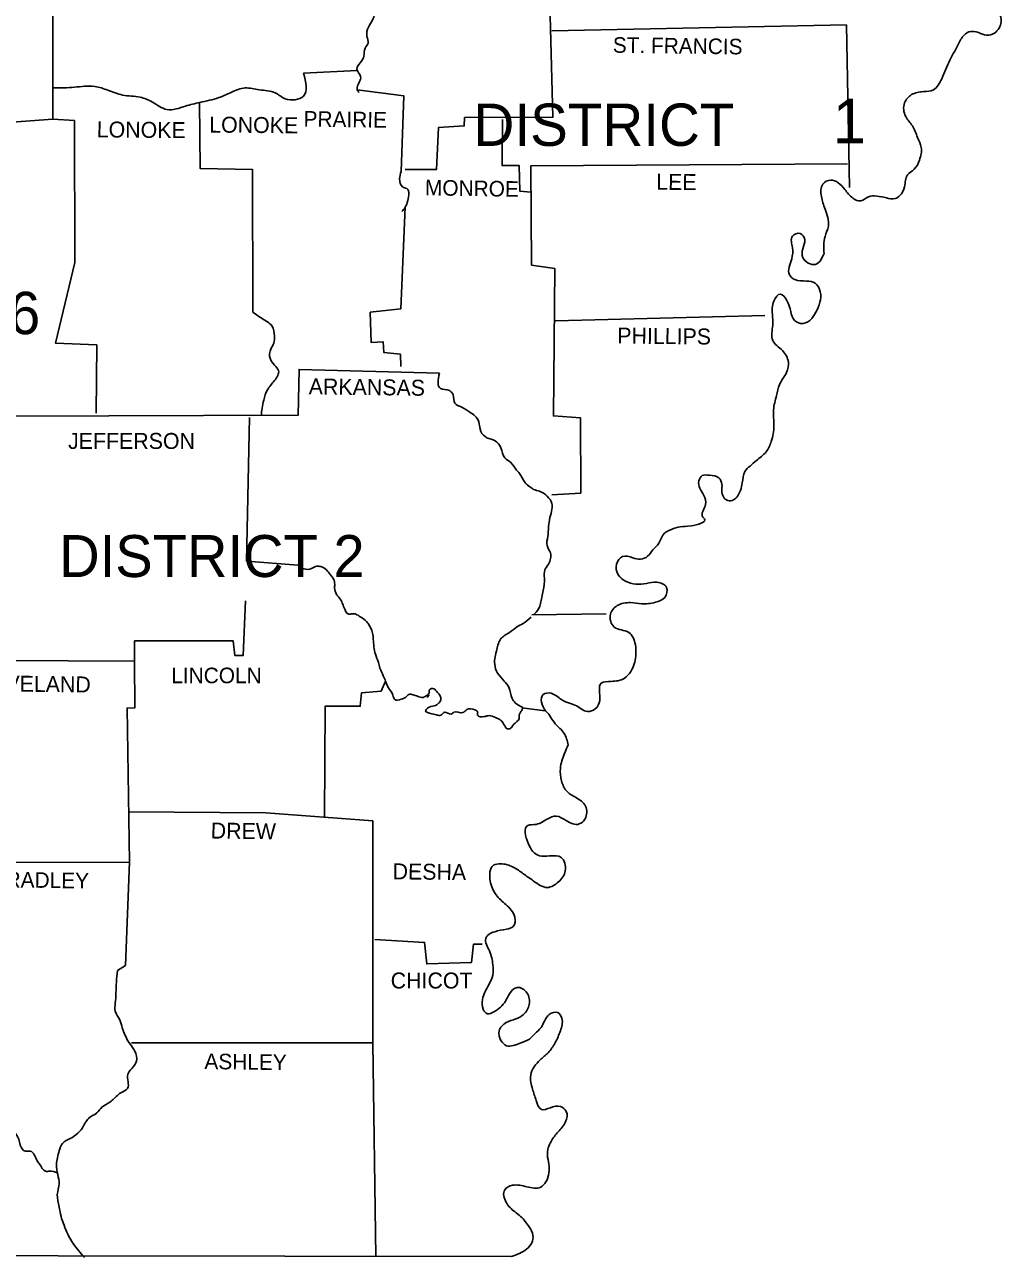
# Model space of a CAD drawing. Extents: x -549 to 3324, y -742 to 2142.
# Drawn here: x 2751.9 to 3009.3, y 1337.5 to 1662.3 of the extents above; entities that cross this region are included whole.
import ezdxf

# ---------------------------------------------------------------- set-up
doc = ezdxf.new("R2010")
doc.units = 0
for name, color, linetype in [('1', 7, 'Continuous'), ('2', 7, 'Continuous'), ('3', 7, 'Continuous')]:
    doc.layers.add(name, color=color, linetype=linetype)

msp = doc.modelspace()

# ---------------------------------------------------------------- linework, layer by layer
at = {"layer": '1'}
msp.add_line((2885.59, 1506.74), (2905.16, 1507.03), dxfattribs=at)
for points in [[(2752.92, 1860.82), (2753.12, 1837.54), (2751.45, 1837.44), (2751.75, 1813.08), (2744.9, 1812.1), (2745.49, 1805.54), (2747.83, 1802.51), (2747.64, 1794.78), (2734.33, 1794.29), (2733.84, 1782.36), (2721.71, 1781.96), (2721.12, 1767.48), (2721.81, 1766.31), (2722.1, 1743.22), (2743.04, 1741.85), (2742.75, 1690.29), (2759.38, 1689.8), (2759.38, 1637.36), (2746.27, 1636.38), (2745.29, 1624.83), (2723.28, 1624.73)], [(2889.7, 1691.46), (2891.17, 1637.84), (2867.89, 1637.75), (2867.79, 1635.59), (2861.04, 1635.2), (2860.45, 1624.05), (2852.23, 1624.05)], [(2890.88, 1660.64), (2968.56, 1662.21)], [(2968.56, 1662.21), (2969.35, 1619.35)], [(2825.42, 1649.49), (2839.61, 1650.17)], [(2839.61, 1645.08), (2851.84, 1643.52), (2851.15, 1623.56)], [(2798.03, 1641.86), (2798.22, 1624.34), (2812.02, 1624.05), (2812.12, 1586.48)], [(2759.38, 1637.36), (2765.05, 1636.96), (2765.15, 1599.59), (2760.06, 1578.36), (2770.93, 1577.87), (2770.83, 1559.87)], [(2877.87, 1637.26), (2877.77, 1625.13), (2882.27, 1625.13), (2882.46, 1618.37), (2885.3, 1618.08)], [(2890.88, 1538.34), (2898.51, 1538.83), (2898.41, 1558.69), (2891.27, 1559.18), (2891.66, 1598.02), (2885.5, 1598.9), (2885.3, 1625.03), (2968.76, 1625.61)], [(2852.23, 1614.17), (2851.06, 1587.36), (2843.03, 1586.48), (2843.23, 1578.55), (2846.46, 1578.65), (2846.56, 1575.91), (2850.96, 1575.42), (2851.06, 1572.19)], [(2891.86, 1584.23), (2947.04, 1585.6)], [(2861.23, 1570.43), (2824.25, 1571.41), (2824.05, 1559.38), (2749.2, 1559.08)], [(2811.24, 1558.79), (2810.45, 1520.92), (2824.05, 1519.85)], [(2810.16, 1510.46), (2809.57, 1496.07), (2807.32, 1496.07), (2806.93, 1499.89), (2780.9, 1499.89), (2780.9, 1494.41)], [(2746.07, 1494.7), (2780.71, 1494.51)], [(2780.9, 1494.51), (2781, 1482.28), (2778.95, 1482.18), (2779.54, 1441.58)], [(2847.05, 1489.32), (2845.87, 1486.68), (2840.69, 1486.19), (2840.39, 1482.67), (2831.1, 1482.67), (2831, 1453.41)], [(2858, 1485.02), (2858.3, 1485.31), (2858.59, 1485.6), (2858.59, 1485.6)], [(2779.24, 1454.88), (2815.54, 1454.59), (2843.72, 1452.44)], [(2843.72, 1452.44), (2843.72, 1393.93), (2844.5, 1337.67)], [(2735.31, 1441.48), (2779.54, 1441.58)], [(2779.54, 1441.58), (2778.56, 1414.38), (2776.4, 1413.01)], [(2844.21, 1421.23), (2857.32, 1420.44), (2857.91, 1414.77), (2869.74, 1415.16), (2870.23, 1419.95), (2872.48, 1419.95)], [(2521.43, 1417.41), (2521.63, 1338.26), (2880.21, 1337.67)], [(2780.12, 1394.03), (2843.72, 1394.03)]]:
    msp.add_lwpolyline(points, dxfattribs=at)
for points in [[(2852.04, 1702.81), (2851.55, 1699.58), (2849.69, 1698.7), (2847.53, 1696.55), (2847.05, 1694.59), (2845.28, 1693.81), (2843.62, 1691.75), (2842.54, 1688.92), (2842.54, 1685.98), (2843.23, 1682.66), (2845.68, 1681.77), (2846.85, 1679.82), (2846.65, 1677.76), (2849, 1676.39), (2849.39, 1675.22), (2849, 1673.95), (2847.93, 1670.33), (2848.02, 1667.88), (2847.83, 1666.81), (2845.19, 1666.12), (2843.62, 1663.48), (2842.54, 1661.62), (2842.15, 1659.17), (2842.45, 1657.41), (2841.66, 1656.04), (2841.37, 1653.99), (2840.39, 1652.23), (2839.51, 1650.56), (2840.49, 1648.61), (2840.2, 1647.24), (2839.61, 1645.08), (2840.1, 1644.4)], [(3005.06, 1698.9), (3005.45, 1696.06), (3003.79, 1693.03), (3003.2, 1689.99), (3003.49, 1686.96), (3000.36, 1685.3), (2997.62, 1683.34), (2999.19, 1680.99), (3002.12, 1678.84), (3005.06, 1677.18), (3006.92, 1675.51), (3007.41, 1671.5), (3007.9, 1668.96), (3008.87, 1665.44), (3009.27, 1662.99), (3007.5, 1660.05), (3005.45, 1659.47), (3003.3, 1660.15), (3000.75, 1660.35), (2998.7, 1658.39), (2997.23, 1655.65), (2995.76, 1652.91), (2994.69, 1650.56), (2993.61, 1648.02), (2991.46, 1645.08), (2988.82, 1644.6), (2985.69, 1643.81), (2983.83, 1641.66), (2984.12, 1638.04), (2985.88, 1635.59), (2987.25, 1632.56), (2988.23, 1629.92), (2987.74, 1626.59), (2986.37, 1624.15), (2984.61, 1622.68), (2983.83, 1619.55), (2982.55, 1617.2), (2981.38, 1616.42), (2979.03, 1616.61), (2976.49, 1617.1), (2974.34, 1616.91), (2972.28, 1615.83), (2970.23, 1616.52), (2968.07, 1618.86), (2966.31, 1620.62), (2964.36, 1621.31), (2962.3, 1620.23), (2961.91, 1617), (2962.89, 1613.68), (2963.77, 1609.18), (2962.89, 1606.44), (2962.6, 1601.94)], [(2759.58, 1645.57), (2765.05, 1645.77), (2770.44, 1645.97), (2773.86, 1644.99), (2777.77, 1643.71), (2782.37, 1643.13), (2785.6, 1641.86), (2789.42, 1639.9), (2794.31, 1640.78), (2798.12, 1641.76), (2803.11, 1643.03), (2806.34, 1644.4), (2810.06, 1645.57), (2813.78, 1645.08), (2817.99, 1644.3), (2820.63, 1642.74), (2825.42, 1643.42), (2825.42, 1649.49)], [(2851.15, 1623.56), (2850.76, 1621.6), (2851.55, 1619.55), (2852.92, 1618.86), (2853.11, 1616.91), (2852.62, 1614.95), (2852.23, 1614.17), (2851.35, 1612.99)], [(2962.6, 1601.94), (2960.34, 1599.1), (2957.02, 1600.86), (2957.02, 1603.21), (2957.51, 1605.65), (2956.33, 1607.22), (2954.28, 1606.54), (2954.28, 1603.5), (2954.08, 1600.57), (2953.5, 1596.36), (2954.87, 1595.09), (2958, 1594.7), (2960.25, 1594.11), (2961.62, 1591.86), (2961.52, 1589.12), (2960.44, 1586.48), (2958.88, 1584.33), (2956.43, 1583.54), (2954.47, 1584.81), (2953.69, 1587.36), (2952.81, 1589.61), (2951.15, 1591.27), (2949.39, 1589.41), (2949, 1585.99), (2949.09, 1583.05), (2949.09, 1579.04), (2951.64, 1576.4), (2953.2, 1573.37), (2952.71, 1570.63), (2950.85, 1567.4), (2950.07, 1564.56), (2949.29, 1560.75), (2949.39, 1556.54), (2948.7, 1552.43), (2947.33, 1549.69), (2944.79, 1547.44), (2943.12, 1545.97), (2941.75, 1544.5), (2941.07, 1541.57), (2940.58, 1539.51), (2938.72, 1537.07), (2937.25, 1536.87), (2936.08, 1537.85), (2935.69, 1539.51), (2935.69, 1541.18), (2934.91, 1542.84), (2932.46, 1543.53), (2930.5, 1543.43), (2929.62, 1542.06), (2930.89, 1538.24), (2931.38, 1535.8), (2930.7, 1532.47), (2931.09, 1532.08), (2927.57, 1530.22), (2924.73, 1529.93), (2922.38, 1529.24), (2920.13, 1527.77), (2919.06, 1525.62), (2917.49, 1523.86), (2916.12, 1522.2), (2914.26, 1521.41), (2912.21, 1521.81), (2909.47, 1522.1), (2907.9, 1520.14), (2908.39, 1517.3), (2910.25, 1515.64), (2912.99, 1514.86), (2915.83, 1515.05), (2918.57, 1515.35), (2921.11, 1513.98), (2920.62, 1511.34), (2918.18, 1510.06), (2914.56, 1509.67), (2911.62, 1509.97), (2908.1, 1509.18), (2906.34, 1506.93), (2907.32, 1503.51), (2911.13, 1502.14), (2912.89, 1498.91), (2912.99, 1495.88), (2911.72, 1491.87), (2909.96, 1490.01), (2906.53, 1489.22), (2903.89, 1488.74), (2903.5, 1484.23), (2902.33, 1481.98), (2900.27, 1481.3), (2897.34, 1482.77), (2895.57, 1483.45), (2893.42, 1484.43), (2890.68, 1486.09), (2888.63, 1485.8), (2889.21, 1481.5), (2889.41, 1481.3), (2891.76, 1478.07), (2894.11, 1475.53), (2895.18, 1472.49)], [(2812.12, 1586.48), (2814.56, 1584.81), (2817.11, 1582.86), (2817.79, 1580.22), (2817.6, 1578.36), (2816.81, 1576.79), (2816.62, 1574.35), (2817.79, 1572.58), (2818.87, 1571.12), (2817.79, 1568.48), (2815.93, 1566.03), (2814.95, 1563.29), (2814.27, 1559.18)], [(2861.23, 1570.43), (2861.53, 1566.42), (2863.87, 1565.83), (2864.85, 1564.76), (2865.34, 1562.51), (2867, 1561.53), (2869.26, 1560.16), (2870.62, 1559.18), (2871.6, 1557.62), (2872.19, 1555.07), (2873.76, 1553.41), (2875.91, 1552.63), (2877.47, 1550.77), (2878.45, 1548.12), (2880.02, 1546.95), (2881.58, 1544.9), (2882.37, 1544.02), (2883.74, 1541.67), (2885.11, 1540.49), (2886.08, 1539.81), (2887.65, 1539.32), (2889.61, 1538.05), (2890.88, 1536.09), (2890.88, 1534.62), (2890.39, 1532.37), (2890, 1530.02), (2889.8, 1527.38), (2889.61, 1525.03), (2890.49, 1523.08), (2890, 1520.14), (2889.02, 1518.58), (2888.92, 1516.42), (2888.63, 1513.2), (2888.24, 1511.34), (2887.36, 1508.3), (2886.08, 1506.74)], [(2824.05, 1519.85), (2825.52, 1518.87), (2827.57, 1518.97), (2828.94, 1519.56), (2830.02, 1519.46), (2831.49, 1518.58), (2832.47, 1517.4), (2833.15, 1516.52), (2833.64, 1515.15), (2833.64, 1513.88), (2834.13, 1512.12), (2834.72, 1511.43), (2835.5, 1510.16), (2835.99, 1508.99), (2836.28, 1508.21), (2837.36, 1506.93), (2838.34, 1507.03), (2839.22, 1506.93), (2840.39, 1506.25), (2842.15, 1504.88), (2842.45, 1504.49), (2843.62, 1501.94), (2843.82, 1500.38), (2844.01, 1498.32), (2844.4, 1496.37), (2845.19, 1494.21), (2845.58, 1492.75), (2846.46, 1490.69), (2847.05, 1489.32), (2847.83, 1487.56), (2849, 1485.6), (2849.49, 1484.43), (2851.15, 1484.53), (2852.33, 1485.02), (2853.21, 1485.8), (2854.29, 1485.7), (2855.46, 1485.31), (2857.02, 1485.02), (2858, 1485.6), (2858.49, 1486), (2858.59, 1486.88), (2859.47, 1487.37), (2860.45, 1486.68), (2861.53, 1485.12), (2861.53, 1484.14), (2861.13, 1483.55), (2859.86, 1482.77), (2858.1, 1482.18), (2857.61, 1481.5), (2859.28, 1480.71), (2861.92, 1480.52), (2862.6, 1481.1), (2864.36, 1480.61), (2865.05, 1481.1), (2867.4, 1481.01), (2868.47, 1481.79), (2870.62, 1481.69), (2871.31, 1481.2), (2871.31, 1480.32), (2873.07, 1479.93), (2874.34, 1480.22), (2876.01, 1479.73), (2877.47, 1478.95), (2878.26, 1477.87), (2879.23, 1476.7), (2880.12, 1476.99), (2880.8, 1477.87), (2882.27, 1479.44), (2882.27, 1480.42), (2882.66, 1481.1), (2883.15, 1482.08)], [(2885.4, 1506.15), (2883.34, 1504.49), (2881.58, 1503.51), (2879.72, 1502.14), (2877.47, 1500.48), (2876.4, 1497.64), (2875.81, 1493.73), (2876.59, 1491.38), (2878.35, 1489.32), (2879.53, 1487.66), (2880.41, 1484.72), (2882.56, 1482.67), (2883.25, 1482.38)], [(2895.18, 1472.49), (2894.2, 1470.24), (2893.13, 1466.33), (2893.42, 1463), (2894.89, 1460.17), (2897.24, 1458.6), (2899.78, 1456.35), (2899.59, 1452.93), (2898.12, 1451.65), (2894.69, 1452.53), (2892.05, 1453.71), (2889.8, 1453.02), (2886.77, 1451.56), (2884.52, 1451.26), (2884.62, 1446.57), (2887.65, 1443.24), (2890.29, 1443.24), (2893.32, 1442.85), (2894.4, 1439.33), (2892.64, 1436.39), (2889.7, 1434.92), (2885.99, 1436.68), (2883.34, 1438.54), (2880.7, 1440.3), (2877.38, 1441.18), (2875.52, 1440.79), (2874.64, 1436.68), (2876.2, 1432.97), (2878.75, 1430.42), (2881.09, 1427.1), (2880.7, 1424.65), (2878.94, 1423.96), (2875.81, 1423.28), (2873.95, 1422.3), (2873.46, 1421.52), (2874.44, 1418.19), (2875.32, 1414.57), (2875.32, 1411.83), (2874.24, 1409.29), (2872.58, 1405.38), (2872.78, 1402.83), (2873.95, 1401.66), (2875.42, 1402.05), (2877.38, 1403.42), (2878.65, 1404.98), (2879.72, 1406.94), (2881.78, 1408.6), (2884.32, 1407.14), (2884.91, 1404.1), (2883.44, 1401.46), (2881.39, 1400.29), (2878.84, 1399.31), (2876.98, 1397.16), (2877.47, 1394.61), (2878.94, 1393.24), (2882.56, 1393.93), (2885.01, 1395), (2886.38, 1396.37), (2888.04, 1398.04), (2888.92, 1399.7), (2890.19, 1401.46), (2892.44, 1401.95), (2893.52, 1400.48), (2893.13, 1397.16), (2891.76, 1394.03), (2889.9, 1391.38), (2887.84, 1389.52), (2885.3, 1385.51), (2885.79, 1381.8), (2886.77, 1378.76), (2888.14, 1376.41), (2890.49, 1376.9), (2893.13, 1377.2), (2894.69, 1375.92), (2894.5, 1373.19), (2892.54, 1370.54), (2890.68, 1368), (2889.7, 1364.48), (2890.1, 1362.03), (2890.1, 1359.78), (2889.31, 1357.34), (2887.94, 1355.97), (2884.32, 1356.06), (2880.51, 1356.45), (2878.45, 1355.28), (2878.84, 1351.95), (2881.09, 1349.51), (2882.66, 1348.24), (2884.91, 1345.5), (2885.89, 1343.25), (2885.59, 1341.29), (2884.22, 1339.63), (2880.21, 1337.67)], [(2776.4, 1413.01), (2776.11, 1409.97), (2776.01, 1407.14), (2775.82, 1404.4), (2775.82, 1402.34), (2776.99, 1400.09), (2777.68, 1397.94), (2778.36, 1396.08), (2779.73, 1393.63), (2781, 1391.78), (2781.39, 1389.13), (2780.61, 1387.76), (2779.14, 1385.71), (2779.05, 1381.99), (2777.28, 1380.82), (2775.03, 1378.86), (2773.76, 1377.98), (2772.39, 1377.1), (2770.93, 1375.53), (2768.77, 1374.07), (2767.21, 1371.62), (2765.45, 1369.76), (2763.98, 1368.78), (2761.92, 1367.51), (2761.04, 1365.55), (2760.36, 1361.93), (2760.65, 1359.29), (2761.04, 1356.94), (2760.55, 1354.01), (2761.04, 1350.78), (2761.53, 1348.24), (2762.32, 1345.99), (2763.39, 1343.44), (2764.76, 1341.09), (2767.7, 1337.47)], [(2678.86, 1390.41), (2680.42, 1391.48), (2681.89, 1392.07), (2683.36, 1391.78), (2684.92, 1391.58), (2686.29, 1391.78), (2688.05, 1391.48), (2689.52, 1390.6), (2691.18, 1389.92), (2692.85, 1389.92), (2694.32, 1389.92), (2695.59, 1389.04), (2697.94, 1389.13), (2699.89, 1389.92), (2701.85, 1390.5), (2704.49, 1390.8), (2706.84, 1389.13), (2708.5, 1387.76), (2709.87, 1386.2), (2710.85, 1384.44), (2711.93, 1383.46), (2713.69, 1382.77), (2715.06, 1382.48), (2716.72, 1381.99), (2717.6, 1381.6), (2718.38, 1379.74), (2719.66, 1377.2), (2722.1, 1376.32), (2725.14, 1377.49), (2727.58, 1378.18), (2729.34, 1378.76), (2730.42, 1379.15), (2731.4, 1379.25), (2731.1, 1379.45), (2732.28, 1379.74), (2733.35, 1378.96), (2734.04, 1377.88), (2735.21, 1376.32), (2736.29, 1374.95), (2737.37, 1374.46), (2738.44, 1375.04), (2739.91, 1374.56), (2741.18, 1374.07), (2742.65, 1373.67), (2743.92, 1373.58), (2745.58, 1373.19), (2746.86, 1372.5), (2748.03, 1371.82), (2749.2, 1370.54), (2750.38, 1368.59), (2750.77, 1367.02), (2752.14, 1365.46), (2753.41, 1365.46), (2755.27, 1362.91), (2755.96, 1361.93), (2757.42, 1360.17), (2758.5, 1360.17), (2760.55, 1359.78)]]:
    msp.add_spline(points, degree=3, dxfattribs=at)
at = {"layer": '3'}
msp.add_line((2882.95, 1482.28), (2889.12, 1481.5), dxfattribs=at)

# ---------------------------------------------------------------- texts
at = {"layer": '1'}
msp.add_text('1', height=11.74, dxfattribs=at).set_placement((2964.94, 1631))
at = {"layer": '2'}
for s, height, rotation, p in [('ST. FRANCIS', 4.1081, 359.2216, (2906.92, 1654.87)), ('LONOKE', 4.207, 359.4974, (2800.57, 1633.83)), ('PRAIRIE', 4.109, 359.2116, (2825.42, 1635.4)), ('LONOKE', 4.207, 359.4974, (2770.93, 1632.56)), ('MONROE', 4.108, 359.0331, (2857.42, 1617.3)), ('LEE', 4.207, 359.4327, (2918.37, 1618.77)), ('PHILLIPS', 4.206, 359.3179, (2908.1, 1578.26)), ('ARKANSAS', 4.206, 359.2678, (2826.79, 1564.86)), ('CLEVELAND', 4.207, 359.3377, (2735.9, 1486.68)), ('DREW', 4.206, 359.2258, (2800.96, 1447.84)), ('BRADLEY', 4.108, 359.1449, (2743.24, 1435.02)), ('DESHA', 4.206, 359.3704, (2848.9, 1437.08)), ('ASHLEY', 4.109, 359.2361, (2799.3, 1387.08))]:
    msp.add_text(s, height=height, rotation=rotation, dxfattribs=at).set_placement(p)
for s, height, p in [('JEFFERSON', 4.207, (2763.39, 1550.47)), ('LINCOLN', 4.109, (2790.59, 1488.74)), ('CHICOT', 4.207, (2848.41, 1408.31))]:
    msp.add_text(s, height=height, dxfattribs=at).set_placement(p)
at = {"layer": '3'}
for s, height, p in [('DISTRICT', 11.154, (2870.23, 1630.31)), ('DISTRICT 6', 11.154, (2674.85, 1580.71)), ('DISTRICT 2', 11.056, (2761.04, 1516.72))]:
    msp.add_text(s, height=height, dxfattribs=at).set_placement(p)

doc.saveas('drawing.dxf')
